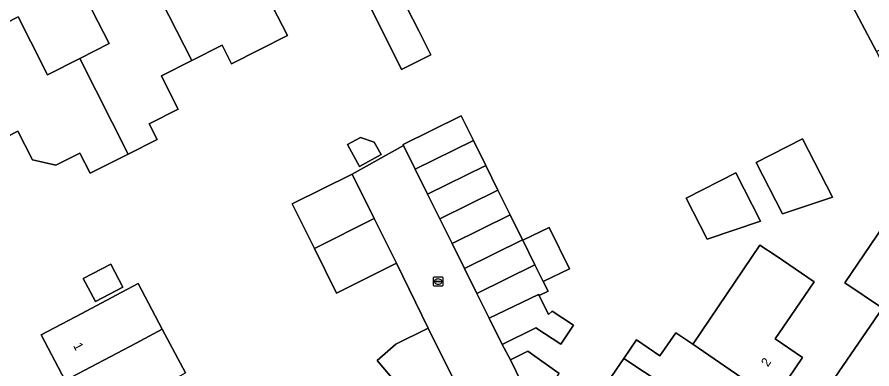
# Model space of a CAD drawing. Extents: x 157320 to 158835, y 386650 to 388491.
# Drawn here: x 157593.5 to 157686.5, y 387598 to 387636.3 of the extents above; entities that cross this region are included whole.
import ezdxf

# ---------------------------------------------------------------- set-up
doc = ezdxf.new("R2010")
doc.units = 0
for name, color, linetype in [('IMGEO_Erf', 7, 'Continuous'), ('IMGEO_Kolk', 7, 'Continuous'), ('IMGEO_Muur', 7, 'Continuous'), ('IMGEO_Pand', 7, 'Continuous'), ('IMGEO_Pand_nummerreeks', 7, 'Continuous'), ('IMGEO_Parkeervlak_open', 7, 'Continuous'), ('IMGEO_Rijbaan_lokaal_open', 7, 'Continuous'), ('IMGEO_Voetpad_open', 7, 'Continuous')]:
    doc.layers.add(name, color=color, linetype=linetype)

msp = doc.modelspace()

# ---------------------------------------------------------------- linework, layer by layer
at = {"layer": 'IMGEO_Erf'}
for points in [[(157637.195, 387634.782), (157638.51, 387632.173), (157635.315, 387630.578), (157630.278, 387640.749), (157633.396, 387642.319), (157634.575, 387639.979)], [(157630.755, 387620.05), (157629.438, 387622.415), (157630.853, 387623.203), (157632.367, 387622.672), (157633.1, 387621.356)], [(157678.933, 387623.056), (157682.186, 387616.71), (157676.751, 387614.891), (157673.891, 387620.471)], [(157671.684, 387619.34), (157674.373, 387614.094), (157668.556, 387612.148), (157666.288, 387616.574)], [(157605.008, 387606.913), (157602.029, 387605.343), (157600.715, 387607.838), (157603.693, 387609.407)]]:
    msp.add_lwpolyline(points, close=True, dxfattribs=at)
for points in [[(157620.186, 387639.663), (157622.911, 387634.271), (157616.844, 387631.204), (157615.822, 387633.225), (157612.524, 387631.558), (157609.21, 387629.883), (157610.249, 387627.828), (157611.041, 387626.261), (157607.88, 387624.664), (157608.735, 387622.972), (157605.61, 387621.392), (157601.464, 387619.297), (157600.35, 387621.501), (157597.737, 387620.18), (157595.183, 387620.749), (157593.601, 387623.879), (157592.556, 387623.351)], [(157696.263, 387637.144), (157694.636, 387636.283), (157696.505, 387632.753), (157698.132, 387633.614), (157700.593, 387634.917), (157700.897, 387634.343), (157700.633, 387634.203), (157702.386, 387630.888), (157702.652, 387631.029), (157705.042, 387626.514), (157698.776, 387623.196), (157696.641, 387622.066), (157692.328, 387630.163), (157689.141, 387628.499), (157686.993, 387632.562), (157682.832, 387640.439)], [(157591, 387634.983), (157593.632, 387636.313), (157595.005, 387633.597), (157596.812, 387630.021), (157600.33, 387631.799), (157603.51, 387633.406), (157601.689, 387637.01)], [(157635.593, 387595.534), (157632.691, 387598.944), (157634.697, 387600.708), (157638.221, 387602.456), (157634.775, 387609.507), (157628.25, 387606.275), (157625.845, 387611.131), (157623.439, 387615.986), (157629.964, 387619.218), (157635.543, 387622.325), (157635.492, 387622.428), (157641.801, 387625.556), (157643.142, 387622.851), (157644.48, 387620.151), (157645.814, 387617.46), (157647.152, 387614.761), (157648.485, 387612.07), (157648.516, 387612.007), (157651.379, 387613.418), (157653.608, 387608.922), (157650.745, 387607.512), (157651.263, 387606.466), (157650.301, 387605.99), (157651.325, 387603.924), (157651.728, 387604.294), (157654.016, 387602.775), (157652.638, 387600.699), (157649.93, 387602.496), (157646.27, 387600.683), (157647.174, 387598.992), (157649.078, 387599.948), (157652.474, 387597.51)], [(157656.917, 387559.848), (157687.645, 387604.627), (157683.532, 387607.372), (157691.95, 387619.773)], [(157658.171, 387597.182), (157659.511, 387599.161), (157660.868, 387601.165), (157663.435, 387599.426), (157665.147, 387601.954), (157666.998, 387600.692), (157667.045, 387600.761), (157674.312, 387611.492), (157676.06, 387610.308), (157680.199, 387607.505), (157677.721, 387603.845), (157675.982, 387601.278), (157678.954, 387599.264), (157675.839, 387594.663)], [(157598.731, 387596.772), (157596.119, 387601.729), (157600.543, 387604.06), (157603.756, 387605.753), (157606.697, 387607.303), (157609.309, 387602.346), (157611.814, 387597.591)]]:
    msp.add_lwpolyline(points, dxfattribs=at)
at = {"layer": 'IMGEO_Kolk'}
for p, q in [((157638.889, 387608.02), (157639.741, 387608.02)), ((157638.814, 387607.094), (157638.814, 387607.946)), ((157639.073, 387607.514), (157639.073, 387607.526)), ((157639.511, 387607.477), (157639.113, 387607.477)), ((157639.116, 387607.563), (157639.514, 387607.563)), ((157639.325, 387607.24), (157639.3, 387607.24)), ((157639.302, 387607.8), (157639.327, 387607.8)), ((157639.557, 387607.526), (157639.557, 387607.514)), ((157639.815, 387607.946), (157639.815, 387607.094)), ((157639.741, 387607.02), (157638.889, 387607.02))]:
    msp.add_line(p, q, dxfattribs=at)
for points in [[(157638.889, 387608.02), (157639.741, 387608.02)], [(157638.814, 387607.094), (157638.814, 387607.946)], [(157639.815, 387607.946), (157639.815, 387607.094)], [(157639.741, 387607.02), (157638.889, 387607.02)]]:
    msp.add_lwpolyline(points, dxfattribs=at)
for centre, radius, start, end in [((157638.891, 387607.944), 0.0765, 91.55205, 178.44795), ((157638.891, 387607.944), 0.0765, 91.55205, 178.44795), ((157639.739, 387607.944), 0.0765, 1.55205, 88.44795), ((157639.739, 387607.944), 0.0765, 1.55205, 88.44795), ((157638.891, 387607.096), 0.0765, 181.55205, 268.44795), ((157638.891, 387607.096), 0.0765, 181.55205, 268.44795), ((157639.113, 387607.523), 0.0403, 85.87752, 175.75265), ((157639.11, 387607.513), 0.0366, 178.93798, 274.71019), ((157639.514, 387607.52), 0.043, 264.86636, 352.45326), ((157639.518, 387607.525), 0.0386, 1.73085, 96.63898), ((157639.739, 387607.096), 0.0765, 271.55205, 358.44795), ((157639.739, 387607.096), 0.0765, 271.55205, 358.44795)]:
    msp.add_arc(centre, radius, start, end, dxfattribs=at)
for centre, major_axis, ratio, start_param, end_param in [((157639.301, 387607.52), (-0.387, 0.002), 0.722429, 4.712389, 7.853982), ((157639.326, 387607.52), (-0.39, 0.002), 0.717154, 1.570796, 4.712389)]:
    msp.add_ellipse(centre, major_axis=major_axis, ratio=ratio, start_param=start_param, end_param=end_param, dxfattribs=at)
at = {"layer": 'IMGEO_Muur'}
for points in [[(157635.543, 387622.325), (157629.964, 387619.218)], [(157634.775, 387609.507), (157638.221, 387602.456)], [(157646.27, 387600.683), (157647.174, 387598.992)]]:
    msp.add_lwpolyline(points, dxfattribs=at)
at = {"layer": 'IMGEO_Pand'}
for points in [[(157696.336, 387642.955), (157696.068, 387642.813), (157694.316, 387646.128), (157694.58, 387646.268), (157694.276, 387646.842), (157691.875, 387645.571), (157690.213, 387644.691), (157688.204, 387648.488), (157686.617, 387647.644), (157681.826, 387645.097), (157680.674, 387644.479), (157680.713, 387644.405), (157682.832, 387640.439), (157686.993, 387632.562), (157694.636, 387636.283), (157696.263, 387637.144), (157698.725, 387638.448)], [(157618.227, 387643.983), (157618.144, 387643.941), (157617.896, 387643.816), (157619.157, 387641.321), (157616.16, 387639.806), (157614.288, 387643.509), (157612.966, 387646.125), (157606.72, 387642.968), (157612.524, 387631.558), (157615.822, 387633.225), (157616.844, 387631.204), (157622.911, 387634.271), (157620.186, 387639.663), (157620.362, 387639.752)], [(157606.72, 387642.968), (157600.314, 387639.731), (157601.689, 387637.01), (157603.51, 387633.406), (157600.33, 387631.799), (157605.61, 387621.392), (157608.735, 387622.972), (157607.88, 387624.664), (157611.041, 387626.261), (157610.249, 387627.828), (157609.21, 387629.883), (157612.524, 387631.558)], [(157634.575, 387639.979), (157633.396, 387642.319), (157630.278, 387640.749), (157635.315, 387630.578), (157638.51, 387632.173), (157637.195, 387634.782)], [(157605.61, 387621.392), (157600.33, 387631.799), (157596.812, 387630.021), (157595.005, 387633.597), (157593.632, 387636.313), (157591, 387634.983), (157590.563, 387635.849), (157589.851, 387636.083), (157587.514, 387634.902), (157587.28, 387634.19), (157587.717, 387633.324), (157587.544, 387633.236), (157592.556, 387623.351), (157593.601, 387623.879), (157595.183, 387620.749), (157597.737, 387620.18), (157600.35, 387621.501), (157601.464, 387619.297)], [(157636.825, 387619.738), (157643.142, 387622.851), (157641.801, 387625.556), (157635.492, 387622.428), (157635.543, 387622.325)], [(157630.755, 387620.05), (157633.1, 387621.356), (157632.367, 387622.672), (157630.853, 387623.203), (157629.438, 387622.415)], [(157682.186, 387616.71), (157678.933, 387623.056), (157673.891, 387620.471), (157676.751, 387614.891)], [(157636.825, 387619.738), (157638.164, 387617.037), (157644.48, 387620.151), (157643.142, 387622.851)], [(157645.814, 387617.46), (157644.48, 387620.151), (157638.164, 387617.037), (157639.497, 387614.347)], [(157632.369, 387614.363), (157629.964, 387619.218), (157623.439, 387615.986), (157625.845, 387611.131)], [(157674.373, 387614.094), (157671.684, 387619.34), (157666.288, 387616.574), (157668.556, 387612.148)], [(157640.835, 387611.647), (157647.152, 387614.761), (157645.814, 387617.46), (157639.497, 387614.347)], [(157648.485, 387612.07), (157647.152, 387614.761), (157640.835, 387611.647), (157642.169, 387608.958)], [(157632.369, 387614.363), (157625.845, 387611.131), (157628.25, 387606.275), (157634.775, 387609.507)], [(157648.516, 387612.007), (157649.833, 387609.351), (157650.745, 387607.512), (157653.608, 387608.922), (157651.379, 387613.418)], [(157649.833, 387609.351), (157648.516, 387612.007), (157648.485, 387612.07), (157642.169, 387608.958), (157643.516, 387606.238)], [(157677.721, 387603.845), (157680.199, 387607.505), (157676.06, 387610.308), (157674.312, 387611.492), (157667.045, 387600.761), (157666.998, 387600.692), (157675.839, 387594.663), (157678.954, 387599.264), (157675.982, 387601.278)], [(157602.029, 387605.343), (157605.008, 387606.913), (157603.693, 387609.407), (157600.715, 387607.838)], [(157650.232, 387606.129), (157650.301, 387605.99), (157651.263, 387606.466), (157650.745, 387607.512), (157649.833, 387609.351), (157643.516, 387606.238), (157644.849, 387603.549)], [(157598.731, 387596.772), (157606.451, 387600.821), (157609.309, 387602.346), (157606.697, 387607.303), (157603.756, 387605.753), (157600.543, 387604.06), (157596.119, 387601.729)], [(157650.301, 387605.99), (157650.232, 387606.129), (157644.849, 387603.549), (157646.27, 387600.683), (157649.93, 387602.496), (157652.638, 387600.699), (157654.016, 387602.775), (157651.728, 387604.294), (157651.325, 387603.924)], [(157638.221, 387602.456), (157634.697, 387600.708), (157632.691, 387598.944), (157635.593, 387595.534), (157635.299, 387595.284), (157638.519, 387592.169), (157641.413, 387596.047)], [(157598.731, 387596.772), (157601.249, 387591.991), (157608.97, 387596.07), (157610.678, 387596.952), (157611.814, 387597.591), (157609.309, 387602.346), (157606.451, 387600.821)], [(157666.998, 387600.692), (157665.147, 387601.954), (157663.435, 387599.426), (157660.868, 387601.165), (157659.511, 387599.161), (157664.003, 387596.179), (157672.806, 387590.185), (157675.839, 387594.663)], [(157647.174, 387598.992), (157648.422, 387596.482), (157647.294, 387594.317), (157648.711, 387593.576), (157649.512, 387593.027), (157652.474, 387597.51), (157649.078, 387599.948)], [(157664.003, 387596.179), (157659.511, 387599.161), (157658.171, 387597.182), (157660.737, 387595.444), (157659.052, 387592.955), (157660.032, 387592.292), (157669.773, 387585.706), (157672.806, 387590.185)]]:
    msp.add_lwpolyline(points, close=True, dxfattribs=at)
at = {"layer": 'IMGEO_Parkeervlak_open'}
msp.add_lwpolyline([(157687.645, 387604.627), (157696.06, 387616.975), (157691.95, 387619.773), (157683.532, 387607.372)], close=True, dxfattribs=at)
at = {"layer": 'IMGEO_Rijbaan_lokaal_open'}
msp.add_lwpolyline([(157648.422, 387596.482), (157647.174, 387598.992), (157646.27, 387600.683), (157644.849, 387603.549), (157643.516, 387606.238), (157642.169, 387608.958), (157640.835, 387611.647), (157639.497, 387614.347), (157638.164, 387617.037), (157636.825, 387619.738), (157635.543, 387622.325), (157629.964, 387619.218), (157632.369, 387614.363), (157634.775, 387609.507), (157638.221, 387602.456), (157641.413, 387596.047)], dxfattribs=at)
at = {"layer": 'IMGEO_Voetpad_open'}
msp.add_lwpolyline([(157704.213, 387619.132), (157706.579, 387620.507), (157709.408, 387622.072), (157710.003, 387622.401), (157710.561, 387622.698), (157709.303, 387625.45), (157707.692, 387624.565), (157697.238, 387618.697), (157696.06, 387616.975), (157687.645, 387604.627), (157656.917, 387559.848), (157659.028, 387558.48)], dxfattribs=at)

# ---------------------------------------------------------------- texts
at = {"layer": 'IMGEO_Pand_nummerreeks'}
for s, rotation, p in [('1', 297.78251, (157599.579, 387600.567)), ('2', 55.89776, (157675.173, 387598.175))]:
    msp.add_text(s, height=1, rotation=rotation, dxfattribs=at).set_placement(p)

doc.saveas('drawing.dxf')
